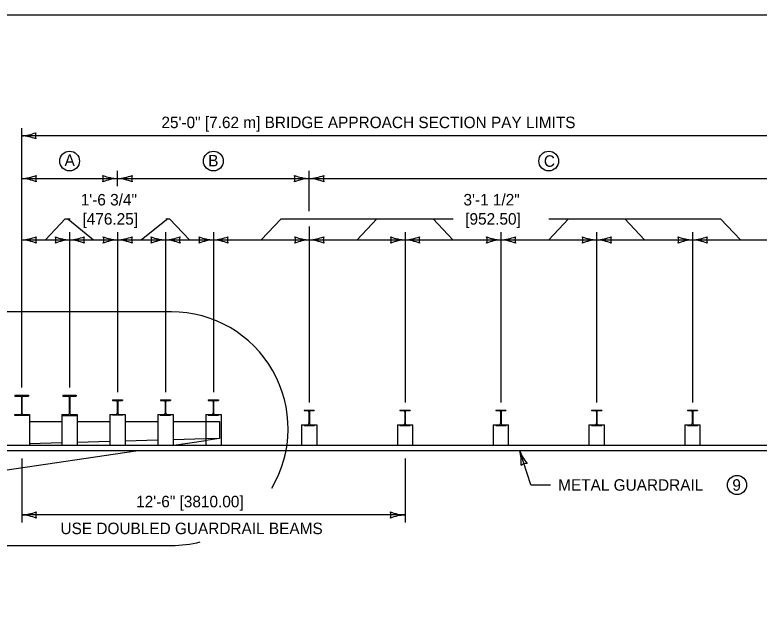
# Model space of a CAD drawing. Extents: x 49991.4 to 50021, y 49987.6 to 50011.4.
# Drawn here: x 50009.785 to 50013.67, y 49995.883 to 49998.999 of the extents above; entities that cross this region are included whole.
import ezdxf

# ---------------------------------------------------------------- set-up
doc = ezdxf.new("R2010")
doc.units = 0
for name, color, linetype in [('Level 1', 7, 'Continuous'), ('Level 2', 7, 'Continuous'), ('Level 3', 7, 'Continuous'), ('Level 4', 7, 'Continuous')]:
    doc.layers.add(name, color=color, linetype=linetype)

msp = doc.modelspace()

# ---------------------------------------------------------------- linework, layer by layer
at = {"layer": 'Level 1'}
for p, q in [((50009.7856, 49997.0148), (50009.8559, 49997.0148)), ((50009.7856, 49997.0148), (50009.7856, 49997.0095)), ((50009.7856, 49997.0095), (50009.8144, 49997.0095)), ((50009.8271, 49997.0095), (50009.8559, 49997.0095)), ((50009.8559, 49997.0148), (50009.8559, 49997.0095)), ((50010.0357, 49997.0148), (50010.106, 49997.0148)), ((50010.0357, 49997.0148), (50010.0357, 49997.0095)), ((50010.0357, 49997.0095), (50010.0646, 49997.0095)), ((50010.0772, 49997.0095), (50010.106, 49997.0095)), ((50010.106, 49997.0148), (50010.106, 49997.0095)), ((50009.8191, 49997.0048), (50009.8191, 49996.9181)), ((50009.8224, 49997.0048), (50009.8224, 49996.9181)), ((50010.0692, 49997.0048), (50010.0692, 49996.9181)), ((50010.0726, 49997.0048), (50010.0726, 49996.9181)), ((50010.2947, 49996.9906), (50010.3473, 49996.9906)), ((50010.2947, 49996.9906), (50010.2947, 49996.9877)), ((50010.2947, 49996.9877), (50010.3127, 49996.9877)), ((50010.3199, 49996.9806), (50010.3199, 49996.9206)), ((50010.3222, 49996.9806), (50010.3222, 49996.9206)), ((50010.3293, 49996.9877), (50010.3473, 49996.9877)), ((50010.3473, 49996.9906), (50010.3473, 49996.9877)), ((50010.5449, 49996.9906), (50010.5974, 49996.9906)), ((50010.5449, 49996.9906), (50010.5449, 49996.9877)), ((50010.5449, 49996.9877), (50010.5629, 49996.9877)), ((50010.57, 49996.9806), (50010.57, 49996.9206)), ((50010.5723, 49996.9806), (50010.5723, 49996.9206)), ((50010.5794, 49996.9877), (50010.5974, 49996.9877)), ((50010.5974, 49996.9906), (50010.5974, 49996.9877)), ((50010.795, 49996.9906), (50010.8476, 49996.9906)), ((50010.795, 49996.9906), (50010.795, 49996.9877)), ((50010.795, 49996.9877), (50010.8131, 49996.9877)), ((50010.8202, 49996.9806), (50010.8202, 49996.9206)), ((50010.8225, 49996.9806), (50010.8225, 49996.9206)), ((50010.8296, 49996.9877), (50010.8476, 49996.9877)), ((50010.8476, 49996.9906), (50010.8476, 49996.9877)), ((50011.2953, 49996.9372), (50011.3479, 49996.9372)), ((50011.2953, 49996.9372), (50011.2953, 49996.9344)), ((50011.2953, 49996.9344), (50011.3133, 49996.9344)), ((50011.3298, 49996.9344), (50011.3479, 49996.9344)), ((50011.3479, 49996.9372), (50011.3479, 49996.9344)), ((50011.7956, 49996.9372), (50011.8481, 49996.9372)), ((50011.7956, 49996.9372), (50011.7956, 49996.9344)), ((50011.7956, 49996.9344), (50011.8136, 49996.9344)), ((50011.8301, 49996.9344), (50011.8481, 49996.9344)), ((50011.8481, 49996.9372), (50011.8481, 49996.9344)), ((50012.2958, 49996.9372), (50012.3484, 49996.9372)), ((50012.2958, 49996.9372), (50012.2958, 49996.9344)), ((50012.2958, 49996.9344), (50012.3138, 49996.9344)), ((50012.3304, 49996.9344), (50012.3484, 49996.9344)), ((50012.3484, 49996.9372), (50012.3484, 49996.9344)), ((50012.7961, 49996.9372), (50012.8486, 49996.9372)), ((50012.7961, 49996.9372), (50012.7961, 49996.9344)), ((50012.7961, 49996.9344), (50012.8141, 49996.9344)), ((50012.8306, 49996.9344), (50012.8486, 49996.9344)), ((50012.8486, 49996.9372), (50012.8486, 49996.9344)), ((50013.2963, 49996.9372), (50013.3489, 49996.9372)), ((50013.2963, 49996.9372), (50013.2963, 49996.9344)), ((50013.2963, 49996.9344), (50013.3144, 49996.9344)), ((50013.3309, 49996.9344), (50013.3489, 49996.9344)), ((50013.3489, 49996.9372), (50013.3489, 49996.9344)), ((50009.8566, 49996.9081), (50009.7849, 49996.9081)), ((50009.7856, 49996.9081), (50009.7856, 49996.9134)), ((50009.7856, 49996.9134), (50009.8144, 49996.9134)), ((50009.8271, 49996.9134), (50009.8559, 49996.9134)), ((50009.8559, 49996.9081), (50009.8559, 49996.9134)), ((50009.8566, 49996.9081), (50009.8566, 49996.9134)), ((50009.8566, 49996.9134), (50009.8608, 49996.9134)), ((50009.8608, 49996.9134), (50009.8608, 49996.7533)), ((50010.0309, 49996.9134), (50010.0309, 49996.7533)), ((50010.0309, 49996.9134), (50010.0351, 49996.9134)), ((50010.0351, 49996.9081), (50010.0351, 49996.9134)), ((50010.0351, 49996.9081), (50010.1067, 49996.9081)), ((50010.0357, 49996.9081), (50010.0357, 49996.9134)), ((50010.0357, 49996.9134), (50010.0646, 49996.9134)), ((50010.0772, 49996.9134), (50010.106, 49996.9134)), ((50010.106, 49996.9081), (50010.106, 49996.9134)), ((50010.1067, 49996.9081), (50010.1067, 49996.9134)), ((50010.1067, 49996.9134), (50010.1109, 49996.9134)), ((50010.1109, 49996.9134), (50010.1109, 49996.7533)), ((50010.281, 49996.9134), (50010.281, 49996.7533)), ((50010.281, 49996.9134), (50010.2941, 49996.9134)), ((50010.2941, 49996.9106), (50010.2941, 49996.9134)), ((50010.348, 49996.9106), (50010.2941, 49996.9106)), ((50010.2947, 49996.9106), (50010.2947, 49996.9134)), ((50010.2947, 49996.9134), (50010.3127, 49996.9134)), ((50010.3293, 49996.9134), (50010.3473, 49996.9134)), ((50010.3473, 49996.9106), (50010.3473, 49996.9134)), ((50010.348, 49996.9106), (50010.348, 49996.9134)), ((50010.348, 49996.9134), (50010.361, 49996.9134)), ((50010.361, 49996.9134), (50010.361, 49996.7533)), ((50010.5311, 49996.9134), (50010.5311, 49996.7533)), ((50010.5311, 49996.9134), (50010.5442, 49996.9134)), ((50010.5442, 49996.9106), (50010.5442, 49996.9134)), ((50010.5442, 49996.9106), (50010.5981, 49996.9106)), ((50010.5449, 49996.9106), (50010.5449, 49996.9134)), ((50010.5449, 49996.9134), (50010.5629, 49996.9134)), ((50010.5794, 49996.9134), (50010.5974, 49996.9134)), ((50010.5974, 49996.9106), (50010.5974, 49996.9134)), ((50010.5981, 49996.9106), (50010.5981, 49996.9134)), ((50010.5981, 49996.9134), (50010.6112, 49996.9134)), ((50010.6112, 49996.9134), (50010.6112, 49996.7533)), ((50010.7813, 49996.9134), (50010.7813, 49996.7533)), ((50010.7813, 49996.9134), (50010.7944, 49996.9134)), ((50010.7944, 49996.9106), (50010.7944, 49996.9134)), ((50010.7944, 49996.9106), (50010.8483, 49996.9106)), ((50010.795, 49996.9106), (50010.795, 49996.9134)), ((50010.795, 49996.9134), (50010.8131, 49996.9134)), ((50010.8296, 49996.9134), (50010.8476, 49996.9134)), ((50010.8476, 49996.9106), (50010.8476, 49996.9134)), ((50010.8483, 49996.9106), (50010.8483, 49996.9134)), ((50010.8483, 49996.9134), (50010.8613, 49996.9134)), ((50010.8613, 49996.9134), (50010.8613, 49996.7533)), ((50011.3204, 49996.9272), (50011.3204, 49996.8672)), ((50011.3227, 49996.9272), (50011.3227, 49996.8672)), ((50011.8207, 49996.9272), (50011.8207, 49996.8672)), ((50011.823, 49996.9272), (50011.823, 49996.8672)), ((50012.321, 49996.9272), (50012.321, 49996.8672)), ((50012.3232, 49996.9272), (50012.3232, 49996.8672)), ((50012.8212, 49996.9272), (50012.8212, 49996.8672)), ((50012.8235, 49996.9272), (50012.8235, 49996.8672)), ((50013.3215, 49996.9272), (50013.3215, 49996.8672)), ((50013.3238, 49996.9272), (50013.3238, 49996.8672)), ((50009.8608, 49996.8767), (50010.0309, 49996.8767)), ((50010.1109, 49996.8767), (50010.281, 49996.8767)), ((50010.361, 49996.8767), (50010.5311, 49996.8767)), ((50010.6112, 49996.8767), (50010.7813, 49996.8767)), ((50011.2816, 49996.8601), (50011.2816, 49996.7533)), ((50011.2816, 49996.8601), (50011.2946, 49996.8601)), ((50011.2946, 49996.8572), (50011.2946, 49996.8601)), ((50011.2946, 49996.8572), (50011.3485, 49996.8572)), ((50011.2953, 49996.8572), (50011.2953, 49996.8601)), ((50011.2953, 49996.8601), (50011.3133, 49996.8601)), ((50011.3298, 49996.8601), (50011.3479, 49996.8601)), ((50011.3479, 49996.8572), (50011.3479, 49996.8601)), ((50011.3485, 49996.8572), (50011.3485, 49996.8601)), ((50011.3485, 49996.8601), (50011.3616, 49996.8601)), ((50011.3616, 49996.8601), (50011.3616, 49996.7533)), ((50011.7818, 49996.8601), (50011.7818, 49996.7533)), ((50011.7818, 49996.8601), (50011.7949, 49996.8601)), ((50011.7949, 49996.8572), (50011.7949, 49996.8601)), ((50011.7949, 49996.8572), (50011.8488, 49996.8572)), ((50011.7956, 49996.8572), (50011.7956, 49996.8601)), ((50011.7956, 49996.8601), (50011.8136, 49996.8601)), ((50011.8301, 49996.8601), (50011.8481, 49996.8601)), ((50011.8481, 49996.8572), (50011.8481, 49996.8601)), ((50011.8488, 49996.8572), (50011.8488, 49996.8601)), ((50011.8488, 49996.8601), (50011.8619, 49996.8601)), ((50011.8619, 49996.7533), (50011.8619, 49996.8601)), ((50012.2821, 49996.8601), (50012.2821, 49996.7533)), ((50012.2821, 49996.8601), (50012.2952, 49996.8601)), ((50012.2952, 49996.8572), (50012.2952, 49996.8601)), ((50012.2952, 49996.8572), (50012.3491, 49996.8572)), ((50012.2958, 49996.8572), (50012.2958, 49996.8601)), ((50012.2958, 49996.8601), (50012.3138, 49996.8601)), ((50012.3304, 49996.8601), (50012.3484, 49996.8601)), ((50012.3484, 49996.8572), (50012.3484, 49996.8601)), ((50012.3491, 49996.8572), (50012.3491, 49996.8601)), ((50012.3491, 49996.8601), (50012.3621, 49996.8601)), ((50012.3621, 49996.7533), (50012.3621, 49996.8601)), ((50012.7823, 49996.8601), (50012.7823, 49996.7533)), ((50012.7823, 49996.8601), (50012.7954, 49996.8601)), ((50012.7954, 49996.8572), (50012.7954, 49996.8601)), ((50012.7954, 49996.8572), (50012.8493, 49996.8572)), ((50012.7961, 49996.8572), (50012.7961, 49996.8601)), ((50012.7961, 49996.8601), (50012.8141, 49996.8601)), ((50012.8306, 49996.8601), (50012.8486, 49996.8601)), ((50012.8486, 49996.8572), (50012.8486, 49996.8601)), ((50012.8493, 49996.8572), (50012.8493, 49996.8601)), ((50012.8493, 49996.8601), (50012.8624, 49996.8601)), ((50012.8624, 49996.7533), (50012.8624, 49996.8601)), ((50013.2826, 49996.8601), (50013.2826, 49996.7533)), ((50013.2826, 49996.8601), (50013.2957, 49996.8601)), ((50013.2957, 49996.8572), (50013.2957, 49996.8601)), ((50013.2957, 49996.8572), (50013.3496, 49996.8572)), ((50013.2963, 49996.8572), (50013.2963, 49996.8601)), ((50013.2963, 49996.8601), (50013.3144, 49996.8601)), ((50013.3309, 49996.8601), (50013.3489, 49996.8601)), ((50013.3489, 49996.8572), (50013.3489, 49996.8601)), ((50013.3496, 49996.8572), (50013.3496, 49996.8601)), ((50013.3496, 49996.8601), (50013.3626, 49996.8601)), ((50013.3626, 49996.7533), (50013.3626, 49996.8601)), ((50010.5311, 49996.7797), (50010.361, 49996.775)), ((50010.7813, 49996.7865), (50010.6112, 49996.7819)), ((50010.6144, 49996.7533), (50010.7813, 49996.778)), ((50009.7324, 49996.7533), (50013.9038, 49996.7533)), ((50010.0309, 49996.7659), (50009.8608, 49996.7612)), ((50010.281, 49996.7728), (50010.1109, 49996.7681)), ((50014.1169, 49996.7242), (50009.6294, 49996.7242)), ((50009.7324, 49996.6233), (50010.4168, 49996.7242))]:
    msp.add_line(p, q, dxfattribs=at)
msp.add_lwpolyline([(49999.3835, 49998.9992), (50016.7501, 49998.9992), (50016.7501, 49987.7988), (49999.3835, 49987.7988)], close=True, dxfattribs=at)
for centre, radius, start, end in [((50009.8144, 49997.0048), 0.00467, 0, 90), ((50009.8271, 49997.0048), 0.00467, 90, 180), ((50010.0646, 49997.0048), 0.00467, 0, 90), ((50010.0772, 49997.0048), 0.00467, 90, 180), ((50010.3127, 49996.9806), 0.00714, 0, 90), ((50010.3293, 49996.9806), 0.00714, 90, 180), ((50010.5629, 49996.9806), 0.00714, 0, 90), ((50010.5794, 49996.9806), 0.00714, 90, 180), ((50010.8131, 49996.9806), 0.00714, 0, 90), ((50010.8296, 49996.9806), 0.00714, 90, 180), ((50011.3133, 49996.9272), 0.00714, 0, 90), ((50011.3298, 49996.9272), 0.00714, 90, 180), ((50011.8136, 49996.9272), 0.00714, 0, 90), ((50011.8301, 49996.9272), 0.00714, 90, 180), ((50012.3138, 49996.9272), 0.00714, 0, 90), ((50012.3304, 49996.9272), 0.00714, 90, 180), ((50012.8141, 49996.9272), 0.00714, 0, 90), ((50012.8306, 49996.9272), 0.00714, 90, 180), ((50013.3144, 49996.9272), 0.00714, 0, 90), ((50013.3309, 49996.9272), 0.00714, 90, 180), ((50009.8144, 49996.9181), 0.00467, 270, 0), ((50009.8271, 49996.9181), 0.00467, 180, 270), ((50010.0646, 49996.9181), 0.00467, 270, 0), ((50010.0772, 49996.9181), 0.00467, 180, 270), ((50010.3127, 49996.9206), 0.00714, 270, 0), ((50010.3293, 49996.9206), 0.00714, 180, 270), ((50010.5629, 49996.9206), 0.00714, 270, 0), ((50010.5794, 49996.9206), 0.00714, 180, 270), ((50010.8131, 49996.9206), 0.00714, 270, 0), ((50010.8296, 49996.9206), 0.00714, 180, 270), ((50011.3133, 49996.8672), 0.00714, 270, 0), ((50011.3298, 49996.8672), 0.00714, 180, 270), ((50011.8136, 49996.8672), 0.00714, 270, 0), ((50011.8301, 49996.8672), 0.00714, 180, 270), ((50012.3138, 49996.8672), 0.00714, 270, 0), ((50012.3304, 49996.8672), 0.00714, 180, 270), ((50012.8141, 49996.8672), 0.00714, 270, 0), ((50012.8306, 49996.8672), 0.00714, 180, 270), ((50013.3144, 49996.8672), 0.00714, 270, 0), ((50013.3309, 49996.8672), 0.00714, 180, 270)]:
    msp.add_arc(centre, radius, start, end, dxfattribs=at)
at = {"layer": 'Level 2'}
for centre, radius in [((50010.0709, 49998.2365), 0.0517), ((50010.8213, 49998.2365), 0.0517), ((50012.5722, 49998.2365), 0.0517), ((50013.5551, 49996.5461), 0.05)]:
    msp.add_circle(centre, radius, dxfattribs=at)
at = {"layer": 'Level 3'}
for p, q in [((50009.8208, 49997.0548), (50009.8208, 49998.4082)), ((50014.756, 49998.3682), (50009.8208, 49998.3682)), ((50010.321, 49998.1047), (50010.321, 49998.1847)), ((50011.3216, 49997.9747), (50011.3216, 49998.1847)), ((50009.8208, 49998.1447), (50013.8229, 49998.1447)), ((50010.0482, 49997.9347), (50009.9449, 49997.8247)), ((50010.0482, 49997.9347), (50010.0743, 49997.9347)), ((50010.0613, 49997.9347), (50010.1951, 49997.8247)), ((50010.5832, 49997.9347), (50010.4457, 49997.8247)), ((50010.5739, 49997.9347), (50010.5926, 49997.9347)), ((50010.5926, 49997.9347), (50010.696, 49997.8247)), ((50011.1747, 49997.9347), (50011.0714, 49997.8247)), ((50011.1747, 49997.9347), (50012.0724, 49997.9347)), ((50011.675, 49997.9347), (50011.5717, 49997.8247)), ((50011.9686, 49997.9347), (50012.072, 49997.8247)), ((50012.572, 49997.9347), (50013.4694, 49997.9347)), ((50012.6755, 49997.9347), (50012.5722, 49997.8247)), ((50012.9692, 49997.9347), (50013.0726, 49997.8247)), ((50013.4694, 49997.9347), (50013.5728, 49997.8247)), ((50010.0709, 49997.8647), (50010.0709, 49997.0548)), ((50010.321, 49997.8647), (50010.321, 49997.0306)), ((50010.5712, 49997.8647), (50010.5712, 49997.0306)), ((50010.8213, 49997.8647), (50010.8213, 49997.0306)), ((50011.3215, 49997.8947), (50011.3215, 49996.9772)), ((50011.8218, 49997.8647), (50011.8218, 49996.9772)), ((50012.3221, 49997.8647), (50012.3221, 49996.9772)), ((50012.8223, 49997.8647), (50012.8223, 49996.9772)), ((50013.3226, 49997.8647), (50013.3226, 49996.9772)), ((50009.8208, 49997.8247), (50013.8229, 49997.8247)), ((50012.4786, 49996.5461), (50012.4207, 49996.7242)), ((50009.8208, 49996.6842), (50009.8208, 49996.3495)), ((50011.8219, 49996.6842), (50011.8219, 49996.3495)), ((50012.4786, 49996.5461), (50012.5811, 49996.5461)), ((50011.8219, 49996.3895), (50009.8208, 49996.3895))]:
    msp.add_line(p, q, dxfattribs=at)
for centre, radius, start, end in [((50009.8096, 49998.595), 0.2271, 272.8273, 292.0772), ((50009.8118, 49998.1517), 0.2167, 67.456, 87.6395), ((50009.9457, 49998.3682), 0.0534, 162.1388, 197.8612), ((50009.8093, 49998.3776), 0.2331, 272.8273, 292.0772), ((50009.8116, 49997.9225), 0.2224, 67.456, 87.6395), ((50009.949, 49998.1447), 0.0548, 162.1388, 197.8612), ((50010.3302, 49998.367), 0.2224, 247.456, 267.6395), ((50010.1927, 49998.1447), 0.0548, 342.1388, 17.8612), ((50010.3325, 49997.9119), 0.2331, 92.8273, 112.0772), ((50010.3095, 49998.3776), 0.2331, 272.8273, 292.0772), ((50010.3119, 49997.9225), 0.2224, 67.456, 87.6395), ((50010.4493, 49998.1447), 0.0548, 162.1388, 197.8612), ((50011.3308, 49998.367), 0.2224, 247.456, 267.6395), ((50011.1933, 49998.1447), 0.0548, 342.1388, 17.8612), ((50011.3331, 49997.9119), 0.2331, 92.8273, 112.0772), ((50011.3101, 49998.3776), 0.2331, 272.8273, 292.0772), ((50011.3125, 49997.9225), 0.2224, 67.456, 87.6395), ((50011.4499, 49998.1447), 0.0548, 162.1388, 197.8612), ((50009.8093, 49998.0576), 0.2331, 272.8273, 292.0772), ((50009.8116, 49997.6025), 0.2224, 67.456, 87.6395), ((50009.949, 49997.8247), 0.0548, 162.1388, 197.8612), ((50010.0798, 49998.0413), 0.2167, 247.456, 267.6395), ((50009.9459, 49997.8247), 0.0534, 342.1388, 17.8612), ((50010.0821, 49997.5979), 0.2271, 92.8273, 112.0772), ((50010.0594, 49998.0576), 0.2331, 272.8273, 292.0772), ((50010.0617, 49997.6025), 0.2224, 67.456, 87.6395), ((50010.1992, 49997.8247), 0.0548, 162.1388, 197.8612), ((50010.3299, 49998.0413), 0.2167, 247.456, 267.6395), ((50010.196, 49997.8247), 0.0534, 342.1388, 17.8612), ((50010.3322, 49997.5979), 0.2271, 92.8273, 112.0772), ((50010.3095, 49998.0576), 0.2331, 272.8273, 292.0772), ((50010.3119, 49997.6025), 0.2224, 67.456, 87.6395), ((50010.4493, 49997.8247), 0.0548, 162.1388, 197.8612), ((50010.5801, 49998.0413), 0.2167, 247.456, 267.6395), ((50010.4462, 49997.8247), 0.0534, 342.1388, 17.8612), ((50010.5824, 49997.5979), 0.2271, 92.8273, 112.0772), ((50010.5597, 49998.0576), 0.2331, 272.8273, 292.0772), ((50010.562, 49997.6025), 0.2224, 67.456, 87.6395), ((50010.6994, 49997.8247), 0.0548, 162.1388, 197.8612), ((50010.8302, 49998.0413), 0.2167, 247.456, 267.6395), ((50010.6963, 49997.8247), 0.0534, 342.1388, 17.8612), ((50010.8325, 49997.5979), 0.2271, 92.8273, 112.0772), ((50010.8098, 49998.0576), 0.2331, 272.8273, 292.0772), ((50010.8121, 49997.6025), 0.2224, 67.456, 87.6395), ((50010.9496, 49997.8247), 0.0548, 162.1388, 197.8612), ((50011.3305, 49998.0413), 0.2167, 247.456, 267.6395), ((50011.1966, 49997.8247), 0.0534, 342.1388, 17.8612), ((50011.3327, 49997.5979), 0.2271, 92.8273, 112.0772), ((50011.31, 49998.0576), 0.2331, 272.8273, 292.0772), ((50011.3124, 49997.6025), 0.2224, 67.456, 87.6395), ((50011.4498, 49997.8247), 0.0548, 162.1388, 197.8612), ((50011.8307, 49998.0413), 0.2167, 247.456, 267.6395), ((50011.6968, 49997.8247), 0.0534, 342.1388, 17.8612), ((50011.833, 49997.5979), 0.2271, 92.8273, 112.0772), ((50011.8103, 49998.0576), 0.2331, 272.8273, 292.0772), ((50011.8126, 49997.6025), 0.2224, 67.456, 87.6395), ((50011.9501, 49997.8247), 0.0548, 162.1388, 197.8612), ((50012.331, 49998.0413), 0.2167, 247.456, 267.6395), ((50012.1971, 49997.8247), 0.0534, 342.1388, 17.8612), ((50012.3333, 49997.5979), 0.2271, 92.8273, 112.0772), ((50012.3106, 49998.0576), 0.2331, 272.8273, 292.0772), ((50012.3129, 49997.6025), 0.2224, 67.456, 87.6395), ((50012.4504, 49997.8247), 0.0548, 162.1388, 197.8612), ((50012.8313, 49998.0413), 0.2167, 247.456, 267.6395), ((50012.6974, 49997.8247), 0.0534, 342.1388, 17.8612), ((50012.8335, 49997.5979), 0.2271, 92.8273, 112.0772), ((50012.8108, 49998.0576), 0.2331, 272.8273, 292.0772), ((50012.8132, 49997.6025), 0.2224, 67.456, 87.6395), ((50012.9506, 49997.8247), 0.0548, 162.1388, 197.8612), ((50013.3315, 49998.0413), 0.2167, 247.456, 267.6395), ((50013.1976, 49997.8247), 0.0534, 342.1388, 17.8612), ((50013.3338, 49997.5979), 0.2271, 92.8273, 112.0772), ((50013.3111, 49998.0576), 0.2331, 272.8273, 292.0772), ((50013.3134, 49997.6025), 0.2224, 67.456, 87.6395), ((50013.4509, 49997.8247), 0.0548, 162.1388, 197.8612), ((50012.212, 49996.6657), 0.2167, 355.4765, 15.66), ((50012.6329, 49996.805), 0.2271, 200.8478, 220.0976), ((50012.4593, 49996.6053), 0.0534, 90.1593, 125.8816), ((50009.8093, 49996.6223), 0.2331, 272.8273, 292.0772), ((50009.8117, 49996.1672), 0.2224, 67.456, 87.6395), ((50009.9491, 49996.3895), 0.0548, 162.1388, 197.8612), ((50011.8311, 49996.6117), 0.2224, 247.456, 267.6395), ((50011.6936, 49996.3895), 0.0548, 342.1388, 17.8612), ((50011.8334, 49996.1566), 0.2331, 92.8273, 112.0772)]:
    msp.add_arc(centre, radius, start, end, dxfattribs=at)
at = {"layer": 'Level 4'}
for p, q in [((50010.6023, 49997.4497), (50009.4126, 49997.4497)), ((50010.7813, 49996.8767), (50010.853, 49996.8767)), ((50010.853, 49996.8767), (50010.853, 49996.7885)), ((50010.853, 49996.7885), (50010.7813, 49996.778)), ((50010.853, 49996.7885), (50010.7813, 49996.7865)), ((50009.4126, 49996.2305), (50010.6023, 49996.2305))]:
    msp.add_line(p, q, dxfattribs=at)
for start, end in [(329.3624, 90), (270, 284.3217)]:
    msp.add_arc((50010.6022, 49996.8401), 0.6096, start, end, dxfattribs=at)

# ---------------------------------------------------------------- texts
at = {"layer": 'Level 2'}
for s, p in [('25\'-0" [7.62 m] BRIDGE APPROACH SECTION PAY LIMITS', (50010.5502, 49998.4082)), ('A', (50010.0447, 49998.211)), ('B', (50010.7944, 49998.2085)), ('C', (50012.5467, 49998.2065)), ('1\'-6 3/4"', (50010.1289, 49998.0047)), ('3\'-1 1/2"', (50012.127, 49998.0047)), ('[476.25]', (50010.1382, 49997.9047)), ('[952.50]', (50012.1363, 49997.9047)), ('METAL GUARDRAIL', (50012.6211, 49996.5161)), ('9', (50013.5307, 49996.5161)), ('12\'-6" [3810.00]', (50010.4183, 49996.4295)), ('USE DOUBLED GUARDRAIL BEAMS', (50010.0234, 49996.2895))]:
    msp.add_text(s, height=0.06, dxfattribs=at).set_placement(p)

doc.saveas('drawing.dxf')
